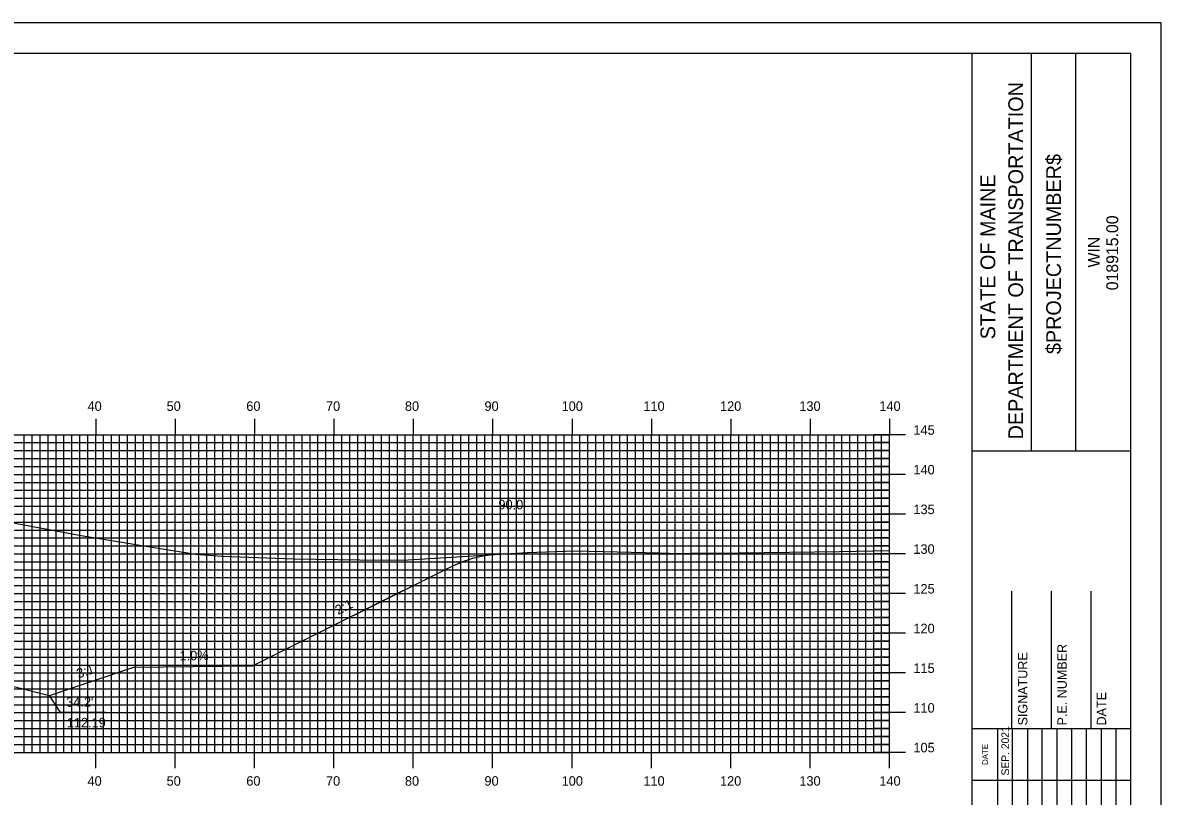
# Model space of a CAD drawing. Extents: x 1768087 to 1768430, y 442591 to 442811.
# Drawn here: x 1768283.8 to 1768427.2, y 442713.1 to 442810.5 of the extents above; entities that cross this region are included whole.
import ezdxf

# ---------------------------------------------------------------- set-up
doc = ezdxf.new("R2010")
doc.units = 0
for name, color, linetype in [('ANNOTATION', 7, 'Continuous'), ('BORDER', 7, 'Continuous'), ('D_Roadway_Centerline', 7, 'Continuous'), ('D_Roadway_SlopeLines', 7, 'Continuous'), ('D_Text_Standard', 7, 'Continuous'), ('H_V ANNOTATION', 7, 'Continuous'), ('MAJOR', 7, 'Continuous'), ('MINOR', 7, 'Continuous'), ('PLOT BOUNDARY', 7, 'Continuous'), ('S_Roadway_Centerline', 7, 'Continuous')]:
    doc.layers.add(name, color=color, linetype=linetype)

msp = doc.modelspace()

# ---------------------------------------------------------------- linework, layer by layer
at = {"layer": 'ANNOTATION'}
msp.add_lwpolyline([(1768294.2, 442723.68), (1768288.51, 442723.68), (1768287.14, 442725.85)], dxfattribs=at)
at = {"layer": 'BORDER'}
for p, q in [((1768403.36, 442596.67), (1768403.36, 442806.67)), ((1768410.82, 442756.66), (1768410.82, 442806.66)), ((1768416.41, 442756.66), (1768416.41, 442806.66)), ((1768403.36, 442756.65), (1768423.36, 442756.65)), ((1768408.36, 442721.67), (1768408.36, 442738.97)), ((1768413.36, 442721.67), (1768413.36, 442738.97)), ((1768418.36, 442721.67), (1768418.36, 442738.97)), ((1768403.36, 442721.67), (1768423.36, 442721.67))]:
    msp.add_line(p, q, dxfattribs=at)
msp.add_lwpolyline([(1768103.36, 442596.67), (1768423.36, 442596.67), (1768423.36, 442806.67), (1768103.36, 442806.67)], close=True, dxfattribs=at)
for points in [[(1768406.59, 442715.17), (1768406.59, 442721.67)], [(1768408.46, 442686.68), (1768408.46, 442721.67)], [(1768410.32, 442721.67), (1768410.32, 442686.68)], [(1768412.18, 442686.68), (1768412.18, 442721.67)], [(1768414.05, 442686.68), (1768414.05, 442721.67)], [(1768415.91, 442686.68), (1768415.91, 442721.67)], [(1768417.77, 442686.68), (1768417.77, 442721.67)], [(1768419.64, 442686.68), (1768419.64, 442721.67)], [(1768421.5, 442686.68), (1768421.5, 442721.67)], [(1768406.59, 442686.68), (1768406.59, 442720.26)], [(1768403.36, 442715.17), (1768423.36, 442715.17)]]:
    msp.add_lwpolyline(points, dxfattribs=at)
at = {"layer": 'D_Roadway_Centerline'}
msp.add_lwpolyline([(1768283.14, 442726.85), (1768287.14, 442725.85), (1768287.14, 442725.85), (1768297.77, 442729.4), (1768312.72, 442729.55), (1768312.73, 442729.55), (1768325.74, 442736.06), (1768337.95, 442742.16), (1768337.96, 442742.17), (1768339.21, 442742.72), (1768339.6, 442742.85), (1768340.46, 442743.14), (1768341.71, 442743.42), (1768342.96, 442743.57)], dxfattribs=at)
at = {"layer": 'D_Roadway_SlopeLines'}
for points in [[(1768297.77, 442729.4), (1768312.72, 442729.55), (1768337.96, 442742.17), (1768339.21, 442742.72), (1768340.46, 442743.14), (1768341.71, 442743.42), (1768342.96, 442743.57)], [(1768272.96, 442729.4), (1768287.14, 442725.85)], [(1768287.14, 442725.85), (1768297.77, 442729.4)]]:
    msp.add_lwpolyline(points, dxfattribs=at)
at = {"layer": 'MAJOR'}
for p, q in [((1768292.96, 442760.67), (1768292.96, 442758.67)), ((1768302.96, 442760.67), (1768302.96, 442758.67)), ((1768312.96, 442760.67), (1768312.96, 442758.67)), ((1768322.96, 442760.67), (1768322.96, 442758.67)), ((1768332.96, 442760.67), (1768332.96, 442758.67)), ((1768342.96, 442760.67), (1768342.96, 442758.67)), ((1768352.96, 442760.67), (1768352.96, 442758.67)), ((1768362.96, 442760.67), (1768362.96, 442758.67)), ((1768372.96, 442760.67), (1768372.96, 442758.67)), ((1768382.96, 442760.67), (1768382.96, 442758.67)), ((1768392.96, 442760.67), (1768392.96, 442758.67)), ((1768112.96, 442758.67), (1768392.96, 442758.67)), ((1768112.96, 442758.67), (1768392.96, 442758.67)), ((1768292.96, 442718.67), (1768292.96, 442758.67)), ((1768302.96, 442718.67), (1768302.96, 442758.67)), ((1768312.96, 442718.67), (1768312.96, 442758.67)), ((1768322.96, 442718.67), (1768322.96, 442758.67)), ((1768332.96, 442718.67), (1768332.96, 442758.67)), ((1768342.96, 442718.67), (1768342.96, 442758.67)), ((1768352.96, 442718.67), (1768352.96, 442758.67)), ((1768362.96, 442718.67), (1768362.96, 442758.67)), ((1768372.96, 442718.67), (1768372.96, 442758.67)), ((1768382.96, 442718.67), (1768382.96, 442758.67)), ((1768394.97, 442758.67), (1768390.96, 442758.67)), ((1768392.96, 442718.67), (1768392.96, 442758.67)), ((1768392.96, 442718.67), (1768392.96, 442758.67)), ((1768112.96, 442753.67), (1768392.96, 442753.67)), ((1768394.97, 442753.67), (1768390.96, 442753.67)), ((1768112.96, 442748.67), (1768392.96, 442748.67)), ((1768394.97, 442748.67), (1768390.96, 442748.67)), ((1768112.96, 442743.67), (1768392.96, 442743.67)), ((1768394.97, 442743.67), (1768390.96, 442743.67)), ((1768112.96, 442738.67), (1768392.96, 442738.67)), ((1768394.97, 442738.67), (1768390.96, 442738.67)), ((1768112.96, 442733.67), (1768392.96, 442733.67)), ((1768394.97, 442733.67), (1768390.96, 442733.67)), ((1768112.96, 442728.67), (1768392.96, 442728.67)), ((1768394.97, 442728.67), (1768390.96, 442728.67)), ((1768112.96, 442723.67), (1768392.96, 442723.67)), ((1768394.97, 442723.67), (1768390.96, 442723.67)), ((1768112.96, 442718.67), (1768392.96, 442718.67)), ((1768112.96, 442718.67), (1768392.96, 442718.67)), ((1768292.96, 442716.66), (1768292.96, 442718.67)), ((1768302.96, 442716.66), (1768302.96, 442718.67)), ((1768312.96, 442716.66), (1768312.96, 442718.67)), ((1768322.96, 442716.66), (1768322.96, 442718.67)), ((1768332.96, 442716.66), (1768332.96, 442718.67)), ((1768342.96, 442716.66), (1768342.96, 442718.67)), ((1768352.96, 442716.66), (1768352.96, 442718.67)), ((1768362.96, 442716.66), (1768362.96, 442718.67)), ((1768372.96, 442716.66), (1768372.96, 442718.67)), ((1768382.96, 442716.66), (1768382.96, 442718.67)), ((1768394.97, 442718.67), (1768390.96, 442718.67)), ((1768392.96, 442716.66), (1768392.96, 442718.67))]:
    msp.add_line(p, q, dxfattribs=at)
at = {"layer": 'MINOR'}
for p, q in [((1768283.96, 442718.67), (1768283.96, 442758.67)), ((1768284.96, 442718.67), (1768284.96, 442758.67)), ((1768285.96, 442718.67), (1768285.96, 442758.67)), ((1768286.96, 442718.67), (1768286.96, 442758.67)), ((1768287.96, 442718.67), (1768287.96, 442758.67)), ((1768288.96, 442718.67), (1768288.96, 442758.67)), ((1768289.96, 442718.67), (1768289.96, 442758.67)), ((1768290.96, 442718.67), (1768290.96, 442758.67)), ((1768291.96, 442718.67), (1768291.96, 442758.67)), ((1768293.96, 442718.67), (1768293.96, 442758.67)), ((1768294.96, 442718.67), (1768294.96, 442758.67)), ((1768295.96, 442718.67), (1768295.96, 442758.67)), ((1768296.96, 442718.67), (1768296.96, 442758.67)), ((1768297.96, 442718.67), (1768297.96, 442758.67)), ((1768298.96, 442718.67), (1768298.96, 442758.67)), ((1768299.96, 442718.67), (1768299.96, 442758.67)), ((1768300.96, 442718.67), (1768300.96, 442758.67)), ((1768301.96, 442718.67), (1768301.96, 442758.67)), ((1768303.96, 442718.67), (1768303.96, 442758.67)), ((1768304.96, 442718.67), (1768304.96, 442758.67)), ((1768305.96, 442718.67), (1768305.96, 442758.67)), ((1768306.96, 442718.67), (1768306.96, 442758.67)), ((1768307.96, 442718.67), (1768307.96, 442758.67)), ((1768308.96, 442718.67), (1768308.96, 442758.67)), ((1768309.96, 442718.67), (1768309.96, 442758.67)), ((1768310.96, 442718.67), (1768310.96, 442758.67)), ((1768311.96, 442718.67), (1768311.96, 442758.67)), ((1768313.96, 442718.67), (1768313.96, 442758.67)), ((1768314.96, 442718.67), (1768314.96, 442758.67)), ((1768315.96, 442718.67), (1768315.96, 442758.67)), ((1768316.96, 442718.67), (1768316.96, 442758.67)), ((1768317.96, 442718.67), (1768317.96, 442758.67)), ((1768318.96, 442718.67), (1768318.96, 442758.67)), ((1768319.96, 442718.67), (1768319.96, 442758.67)), ((1768320.96, 442718.67), (1768320.96, 442758.67)), ((1768321.96, 442718.67), (1768321.96, 442758.67)), ((1768323.96, 442718.67), (1768323.96, 442758.67)), ((1768324.96, 442718.67), (1768324.96, 442758.67)), ((1768325.96, 442718.67), (1768325.96, 442758.67)), ((1768326.96, 442718.67), (1768326.96, 442758.67)), ((1768327.96, 442718.67), (1768327.96, 442758.67)), ((1768328.96, 442718.67), (1768328.96, 442758.67)), ((1768329.96, 442718.67), (1768329.96, 442758.67)), ((1768330.96, 442718.67), (1768330.96, 442758.67)), ((1768331.96, 442718.67), (1768331.96, 442758.67)), ((1768333.96, 442718.67), (1768333.96, 442758.67)), ((1768334.96, 442718.67), (1768334.96, 442758.67)), ((1768335.96, 442718.67), (1768335.96, 442758.67)), ((1768336.96, 442718.67), (1768336.96, 442758.67)), ((1768337.96, 442718.67), (1768337.96, 442758.67)), ((1768338.96, 442718.67), (1768338.96, 442758.67)), ((1768339.96, 442718.67), (1768339.96, 442758.67)), ((1768340.96, 442718.67), (1768340.96, 442758.67)), ((1768341.96, 442718.67), (1768341.96, 442758.67)), ((1768343.96, 442718.67), (1768343.96, 442758.67)), ((1768344.96, 442718.67), (1768344.96, 442758.67)), ((1768345.96, 442718.67), (1768345.96, 442758.67)), ((1768346.96, 442718.67), (1768346.96, 442758.67)), ((1768347.96, 442718.67), (1768347.96, 442758.67)), ((1768348.96, 442718.67), (1768348.96, 442758.67)), ((1768349.96, 442718.67), (1768349.96, 442758.67)), ((1768350.96, 442718.67), (1768350.96, 442758.67)), ((1768351.96, 442718.67), (1768351.96, 442758.67)), ((1768353.96, 442718.67), (1768353.96, 442758.67)), ((1768354.96, 442718.67), (1768354.96, 442758.67)), ((1768355.96, 442718.67), (1768355.96, 442758.67)), ((1768356.96, 442718.67), (1768356.96, 442758.67)), ((1768357.96, 442718.67), (1768357.96, 442758.67)), ((1768358.96, 442718.67), (1768358.96, 442758.67)), ((1768359.96, 442718.67), (1768359.96, 442758.67)), ((1768360.96, 442718.67), (1768360.96, 442758.67)), ((1768361.96, 442718.67), (1768361.96, 442758.67)), ((1768363.96, 442718.67), (1768363.96, 442758.67)), ((1768364.96, 442718.67), (1768364.96, 442758.67)), ((1768365.96, 442718.67), (1768365.96, 442758.67)), ((1768366.96, 442718.67), (1768366.96, 442758.67)), ((1768367.96, 442718.67), (1768367.96, 442758.67)), ((1768368.96, 442718.67), (1768368.96, 442758.67)), ((1768369.96, 442718.67), (1768369.96, 442758.67)), ((1768370.96, 442718.67), (1768370.96, 442758.67)), ((1768371.96, 442718.67), (1768371.96, 442758.67)), ((1768373.96, 442718.67), (1768373.96, 442758.67)), ((1768374.96, 442718.67), (1768374.96, 442758.67)), ((1768375.96, 442718.67), (1768375.96, 442758.67)), ((1768376.96, 442718.67), (1768376.96, 442758.67)), ((1768377.96, 442718.67), (1768377.96, 442758.67)), ((1768378.96, 442718.67), (1768378.96, 442758.67)), ((1768379.96, 442718.67), (1768379.96, 442758.67)), ((1768380.96, 442718.67), (1768380.96, 442758.67)), ((1768381.96, 442718.67), (1768381.96, 442758.67)), ((1768383.96, 442718.67), (1768383.96, 442758.67)), ((1768384.96, 442718.67), (1768384.96, 442758.67)), ((1768385.96, 442718.67), (1768385.96, 442758.67)), ((1768386.96, 442718.67), (1768386.96, 442758.67)), ((1768387.96, 442718.67), (1768387.96, 442758.67)), ((1768388.96, 442718.67), (1768388.96, 442758.67)), ((1768389.96, 442718.67), (1768389.96, 442758.67)), ((1768390.96, 442718.67), (1768390.96, 442758.67)), ((1768391.96, 442718.67), (1768391.96, 442758.67)), ((1768112.96, 442757.67), (1768392.96, 442757.67)), ((1768392.96, 442757.67), (1768390.96, 442757.67)), ((1768112.96, 442756.67), (1768392.96, 442756.67)), ((1768112.96, 442755.67), (1768392.96, 442755.67)), ((1768392.96, 442756.67), (1768390.96, 442756.67)), ((1768392.96, 442755.67), (1768390.96, 442755.67)), ((1768112.96, 442754.67), (1768392.96, 442754.67)), ((1768392.96, 442754.67), (1768390.96, 442754.67)), ((1768112.96, 442752.67), (1768392.96, 442752.67)), ((1768392.96, 442752.67), (1768390.96, 442752.67)), ((1768112.96, 442751.67), (1768392.96, 442751.67)), ((1768392.96, 442751.67), (1768390.96, 442751.67)), ((1768112.96, 442750.67), (1768392.96, 442750.67)), ((1768392.96, 442750.67), (1768390.96, 442750.67)), ((1768112.96, 442749.67), (1768392.96, 442749.67)), ((1768392.96, 442749.67), (1768390.96, 442749.67)), ((1768112.96, 442747.67), (1768392.96, 442747.67)), ((1768392.96, 442747.67), (1768390.96, 442747.67)), ((1768112.96, 442746.67), (1768392.96, 442746.67)), ((1768112.96, 442745.67), (1768392.96, 442745.67)), ((1768392.96, 442746.67), (1768390.96, 442746.67)), ((1768392.96, 442745.67), (1768390.96, 442745.67)), ((1768112.96, 442744.67), (1768392.96, 442744.67)), ((1768392.96, 442744.67), (1768390.96, 442744.67)), ((1768112.96, 442742.67), (1768392.96, 442742.67)), ((1768392.96, 442742.67), (1768390.96, 442742.67)), ((1768112.96, 442741.67), (1768392.96, 442741.67)), ((1768392.96, 442741.67), (1768390.96, 442741.67)), ((1768112.96, 442740.67), (1768392.96, 442740.67)), ((1768392.96, 442740.67), (1768390.96, 442740.67)), ((1768112.96, 442739.67), (1768392.96, 442739.67)), ((1768392.96, 442739.67), (1768390.96, 442739.67)), ((1768112.96, 442737.67), (1768392.96, 442737.67)), ((1768392.96, 442737.67), (1768390.96, 442737.67)), ((1768112.96, 442736.67), (1768392.96, 442736.67)), ((1768112.96, 442735.67), (1768392.96, 442735.67)), ((1768392.96, 442736.67), (1768390.96, 442736.67)), ((1768392.96, 442735.67), (1768390.96, 442735.67)), ((1768112.96, 442734.67), (1768392.96, 442734.67)), ((1768392.96, 442734.67), (1768390.96, 442734.67)), ((1768112.96, 442732.67), (1768392.96, 442732.67)), ((1768392.96, 442732.67), (1768390.96, 442732.67)), ((1768112.96, 442731.67), (1768392.96, 442731.67)), ((1768392.96, 442731.67), (1768390.96, 442731.67)), ((1768112.96, 442730.67), (1768392.96, 442730.67)), ((1768392.96, 442730.67), (1768390.96, 442730.67)), ((1768112.96, 442729.67), (1768392.96, 442729.67)), ((1768392.96, 442729.67), (1768390.96, 442729.67)), ((1768112.96, 442727.67), (1768392.96, 442727.67)), ((1768392.96, 442727.67), (1768390.96, 442727.67)), ((1768112.96, 442726.67), (1768392.96, 442726.67)), ((1768112.96, 442725.67), (1768392.96, 442725.67)), ((1768392.96, 442726.67), (1768390.96, 442726.67)), ((1768392.96, 442725.67), (1768390.96, 442725.67)), ((1768112.96, 442724.67), (1768392.96, 442724.67)), ((1768392.96, 442724.67), (1768390.96, 442724.67)), ((1768112.96, 442722.67), (1768392.96, 442722.67)), ((1768392.96, 442722.67), (1768390.96, 442722.67)), ((1768112.96, 442721.67), (1768392.96, 442721.67)), ((1768392.96, 442721.67), (1768390.96, 442721.67)), ((1768112.96, 442720.67), (1768392.96, 442720.67)), ((1768112.96, 442719.67), (1768392.96, 442719.67)), ((1768392.96, 442720.67), (1768390.96, 442720.67)), ((1768392.96, 442719.67), (1768390.96, 442719.67))]:
    msp.add_line(p, q, dxfattribs=at)
at = {"layer": 'PLOT BOUNDARY'}
msp.add_lwpolyline([(1768087.18, 442590.55), (1768427.18, 442590.55), (1768427.18, 442810.55), (1768087.18, 442810.55)], close=True, dxfattribs=at)
at = {"layer": 'S_Roadway_Centerline'}
msp.add_lwpolyline([(1768281.68, 442747.76), (1768290.88, 442746.03), (1768300.83, 442744.39), (1768305.56, 442743.64), (1768308.86, 442743.38), (1768317.9, 442743.03), (1768329.01, 442742.86), (1768332.3, 442742.92), (1768347.32, 442743.83), (1768353.34, 442744.03), (1768363.95, 442743.79), (1768366.5, 442743.72), (1768367.96, 442743.76), (1768374, 442743.8), (1768386.64, 442743.97), (1768392.96, 442744.09)], dxfattribs=at)

# ---------------------------------------------------------------- texts
at = {"layer": 'ANNOTATION'}
for s, rotation, p in [('2:1', 26.5657, (1768323.49, 442735.96)), ('1.0%', 0.5709, (1768303.53, 442730.25)), ('3:1', 18.4377, (1768290.79, 442727.98))]:
    msp.add_text(s, height=1.2, rotation=rotation, dxfattribs=at).set_placement(p)
for s, p in [("34.2'", (1768289.25, 442724.41)), ('112.19', (1768289.32, 442721.81))]:
    msp.add_text(s, height=1.2, dxfattribs=at).set_placement(p)
at = {"layer": 'BORDER'}
for s, height, p in [('DEPARTMENT OF TRANSPORTATION', 1.8635, (1768409.78, 442758.08)), ('$PROJECTNUMBER$', 1.8635, (1768414.55, 442768.82)), ('STATE OF MAINE', 1.8635, (1768406.27, 442770.69)), ('018915.00', 1.491, (1768421.75, 442776.86)), ('WIN', 1.491, (1768419.44, 442779.73)), ('SIGNATURE', 1.181, (1768410.32, 442722.06)), ('P.E. NUMBER', 1.1811, (1768415.28, 442722.06)), ('DATE', 1.181, (1768420.24, 442722.06)), ('SEP. 2021', 0.969, (1768408.01, 442715.76)), ('DATE', 0.743, (1768405.37, 442717.08))]:
    msp.add_text(s, height=height, rotation=90, dxfattribs=at).set_placement(p)
at = {"layer": 'D_Text_Standard'}
msp.add_text("90.0'", height=1.2, dxfattribs=at).set_placement((1768343.69, 442749.27))
at = {"layer": 'H_V ANNOTATION'}
for s, p in [('40', (1768291.93, 442761.67)), ('50', (1768301.89, 442761.67)), ('60', (1768311.93, 442761.67)), ('70', (1768321.97, 442761.67)), ('80', (1768331.91, 442761.67)), ('90', (1768341.93, 442761.67)), ('100', (1768351.65, 442761.67)), ('110', (1768361.95, 442761.67)), ('120', (1768371.6, 442761.67)), ('130', (1768381.59, 442761.67)), ('140', (1768391.67, 442761.67)), ('145', (1768395.96, 442758.67)), ('140', (1768395.96, 442753.67)), ('135', (1768395.96, 442748.67)), ('130', (1768395.96, 442743.67)), ('125', (1768395.96, 442738.67)), ('120', (1768395.96, 442733.67)), ('115', (1768395.96, 442728.67)), ('110', (1768395.96, 442723.67)), ('105', (1768395.96, 442718.67)), ('40', (1768291.93, 442714.47)), ('50', (1768301.89, 442714.47)), ('60', (1768311.93, 442714.47)), ('70', (1768321.97, 442714.47)), ('80', (1768331.91, 442714.47)), ('90', (1768341.93, 442714.47)), ('100', (1768351.65, 442714.47)), ('110', (1768361.95, 442714.47)), ('120', (1768371.6, 442714.47)), ('130', (1768381.59, 442714.47)), ('140', (1768391.67, 442714.47))]:
    msp.add_text(s, height=1.2, dxfattribs=at).set_placement(p)

doc.saveas('drawing.dxf')
